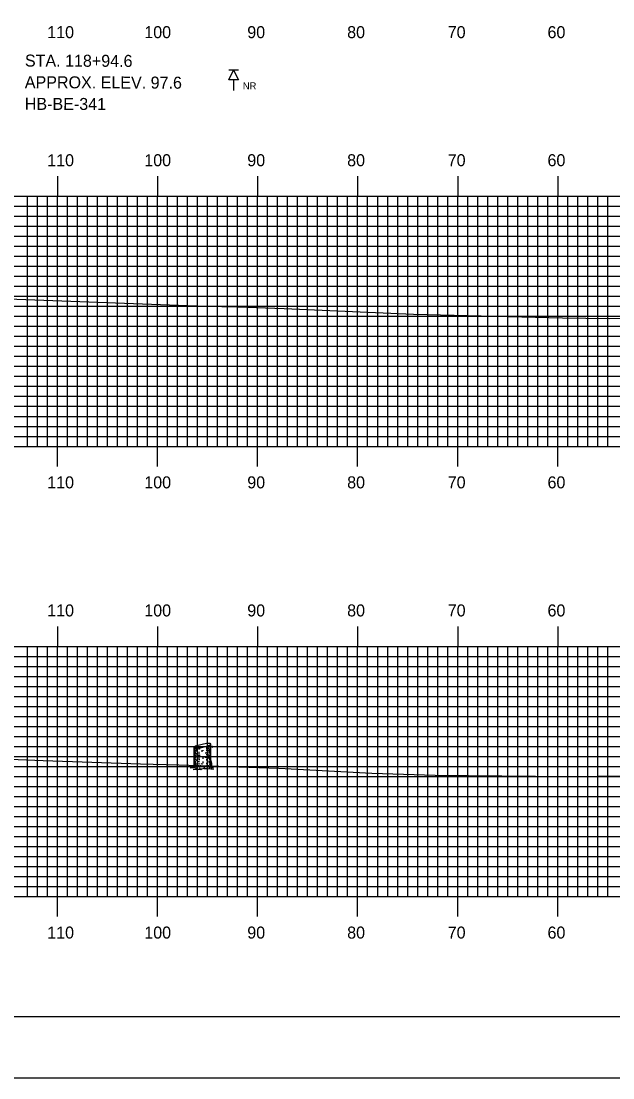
# Model space of a CAD drawing. Extents: x 1771629 to 1771972, y 442591 to 442811.
# Drawn here: x 1771681 to 1771740.1, y 442590.5 to 442696.2 of the extents above; entities that cross this region are included whole.
import ezdxf

# ---------------------------------------------------------------- set-up
doc = ezdxf.new("R2010")
doc.units = 0
for name, color, linetype in [('BORDER', 7, 'Continuous'), ('BORING - NO REFUSAL', 7, 'Continuous'), ('H_V ANNOTATION', 7, 'Continuous'), ('M_Trees_Conifer_Pay', 7, 'Continuous'), ('MAJOR', 7, 'Continuous'), ('MINOR', 7, 'Continuous'), ('PLOT BOUNDARY', 7, 'Continuous'), ('S_Roadway_Centerline', 7, 'Continuous')]:
    doc.layers.add(name, color=color, linetype=linetype)

msp = doc.modelspace()

# ---------------------------------------------------------------- linework, layer by layer
at = {"layer": 'BORDER'}
msp.add_lwpolyline([(1771644.98, 442596.67), (1771964.98, 442596.67), (1771964.98, 442806.67), (1771644.98, 442806.67)], close=True, dxfattribs=at)
at = {"layer": 'BORING - NO REFUSAL'}
for p, q in [((1771702.66, 442691.27), (1771701.7, 442691.27)), ((1771702.18, 442690.31), (1771702.18, 442689.25))]:
    msp.add_line(p, q, dxfattribs=at)
msp.add_lwpolyline([(1771702.18, 442691.27), (1771702.66, 442690.31), (1771701.7, 442690.31)], close=True, dxfattribs=at)
at = {"layer": 'M_Trees_Conifer_Pay'}
for p, q in [((1771698.25, 442621.86), (1771698.25, 442623.58)), ((1771699.49, 442623.59), (1771699.49, 442623.39)), ((1771699.72, 442623.78), (1771699.72, 442623.56)), ((1771699.84, 442623.84), (1771699.84, 442623.68)), ((1771699.84, 442623.61), (1771699.84, 442623.49)), ((1771699.91, 442622.27), (1771699.91, 442623.92)), ((1771698.29, 442623.54), (1771698.29, 442623.07)), ((1771698.29, 442623.01), (1771698.29, 442622.7)), ((1771698.29, 442622.65), (1771698.29, 442622.16)), ((1771698.35, 442623.53), (1771698.35, 442623.43)), ((1771698.35, 442623.36), (1771698.35, 442623.16)), ((1771698.35, 442623.1), (1771698.35, 442622.9)), ((1771698.35, 442622.85), (1771698.35, 442622.52)), ((1771698.48, 442623.52), (1771698.48, 442623.29)), ((1771698.48, 442623.25), (1771698.48, 442623.18)), ((1771698.48, 442622.77), (1771698.48, 442622.64)), ((1771698.7, 442623.54), (1771698.7, 442623.38)), ((1771698.7, 442623.14), (1771698.7, 442622.9)), ((1771698.7, 442622.66), (1771698.7, 442622.51)), ((1771699.1, 442623.31), (1771699.1, 442623.22)), ((1771699.1, 442622.7), (1771699.1, 442622.63)), ((1771699.1, 442622.6), (1771699.1, 442622.45)), ((1771699.49, 442623.33), (1771699.49, 442623.24)), ((1771699.49, 442622.89), (1771699.49, 442622.79)), ((1771699.72, 442623.47), (1771699.72, 442623.42)), ((1771699.72, 442623.09), (1771699.72, 442622.96)), ((1771699.72, 442622.85), (1771699.72, 442622.74)), ((1771699.72, 442622.6), (1771699.72, 442622.46)), ((1771699.78, 442623.29), (1771699.73, 442623.23)), ((1771699.84, 442623.3), (1771699.84, 442622.96)), ((1771699.84, 442622.93), (1771699.84, 442622.76)), ((1771699.84, 442622.72), (1771699.84, 442622.5)), ((1771698.29, 442622.11), (1771698.29, 442621.86)), ((1771698.35, 442622.46), (1771698.35, 442622.33)), ((1771698.35, 442622.23), (1771698.35, 442621.85)), ((1771698.48, 442622.36), (1771698.48, 442622.22)), ((1771698.48, 442621.96), (1771698.48, 442621.87)), ((1771698.48, 442621.47), (1771698.64, 442621.53)), ((1771698.7, 442622.46), (1771698.7, 442622.29)), ((1771698.7, 442622.01), (1771698.7, 442621.86)), ((1771698.91, 442621.4), (1771698.79, 442621.47)), ((1771699.1, 442622.16), (1771699.1, 442622.01)), ((1771699.49, 442622.42), (1771699.49, 442622.28)), ((1771699.49, 442622.04), (1771699.49, 442621.95)), ((1771699.72, 442622.23), (1771699.72, 442622.06)), ((1771699.84, 442622.47), (1771699.84, 442622.39)), ((1771699.84, 442622.35), (1771699.84, 442622.18))]:
    msp.add_line(p, q, dxfattribs=at)
for points in [[(1771699.73, 442623.41), (1771699.76, 442623.34), (1771699.81, 442623.4), (1771699.87, 442623.47), (1771699.96, 442623.66), (1771700.03, 442623.71), (1771700.06, 442623.71)], [(1771699.74, 442623.16), (1771699.78, 442623.29), (1771699.84, 442623.4), (1771699.87, 442623.47), (1771699.94, 442623.62)], [(1771699.96, 442623.65), (1771700.03, 442623.66), (1771700.1, 442623.56)], [(1771698.43, 442622.89), (1771698.42, 442622.98), (1771698.46, 442622.96), (1771698.46, 442622.86)], [(1771699.56, 442622.49), (1771699.58, 442622.41), (1771699.62, 442622.42), (1771699.61, 442622.59)], [(1771699.69, 442623.38), (1771699.66, 442623.29), (1771699.66, 442623.22), (1771699.69, 442623.16)], [(1771699.91, 442622.27), (1771699.96, 442622.01), (1771699.98, 442621.73), (1771700.04, 442621.61), (1771700.17, 442621.58), (1771699.94, 442621.54), (1771699.94, 442621.54), (1771699.95, 442621.49), (1771700.19, 442621.4), (1771699.92, 442621.41), (1771699.56, 442621.44), (1771699.24, 442621.42), (1771699.25, 442621.51), (1771699.1, 442621.42), (1771698.91, 442621.4), (1771698.94, 442621.33), (1771698.67, 442621.38), (1771698.45, 442621.35), (1771698.16, 442621.37), (1771698.45, 442621.42), (1771698.48, 442621.47), (1771698.31, 442621.52), (1771698.08, 442621.53), (1771697.84, 442621.53), (1771698.18, 442621.59), (1771698.22, 442621.67), (1771698.25, 442621.86)], [(1771698.29, 442621.81), (1771698.27, 442621.73), (1771698.25, 442621.64)], [(1771698.37, 442621.79), (1771698.38, 442621.68), (1771698.32, 442621.59), (1771698.31, 442621.52)], [(1771698.53, 442621.82), (1771698.53, 442621.69), (1771698.45, 442621.59)], [(1771698.76, 442621.58), (1771698.83, 442621.67), (1771698.86, 442621.81)], [(1771699.25, 442621.51), (1771699.32, 442621.65), (1771699.33, 442621.75)], [(1771699.5, 442621.88), (1771699.51, 442621.75), (1771699.58, 442621.71)], [(1771699.78, 442621.49), (1771699.76, 442621.62), (1771699.69, 442621.75)], [(1771699.74, 442621.98), (1771699.81, 442621.88), (1771699.82, 442621.7), (1771699.94, 442621.54)], [(1771699.84, 442622.13), (1771699.84, 442621.98), (1771699.89, 442621.91), (1771699.9, 442621.71)]]:
    msp.add_lwpolyline(points, dxfattribs=at)
for centre, radius, start, end in [((1771698.32, 442623.56), 0.0817, 132.3887, 146.7194), ((1771698.3, 442623.57), 0.0527, 146.7194, 156.5158), ((1771698.28, 442623.58), 0.0314, 156.5158, 169.2194), ((1771698.27, 442623.58), 0.0264, 169.2194, 180.0315), ((1771698.27, 442623.58), 0.0226, 180.0315, 191.7194), ((1771698.27, 442623.58), 0.0226, 191.7194, 203.4074), ((1771698.44, 442623.43), 0.251, 124.2194, 132.3887), ((1771698.74, 442622.97), 0.802, 108.0594, 124.2194), ((1771700.1, 442618.81), 5.18, 101.7194, 108.0594), ((1771698.05, 442628.68), 5.18, 275.3794, 281.7194), ((1771700.1, 442618.81), 5.18, 95.3794, 101.7194), ((1771698.05, 442628.68), 5.18, 281.7194, 288.0594), ((1771699.69, 442623.17), 0.802, 79.2194, 95.3794), ((1771699.41, 442624.52), 0.802, 288.0594, 304.2194), ((1771699.58, 442624.23), 0.571, 284.4317, 292.4132), ((1771699.79, 442623.71), 0.251, 71.0501, 79.2194), ((1771699.58, 442624.08), 0.571, 297.0237, 300), ((1771699.72, 442624.07), 0.251, 304.2194, 312.3887), ((1771699.78, 442623.88), 0.172, 300, 311.2506), ((1771699.78, 442623.73), 0.172, 300, 311.2506), ((1771699.85, 442623.87), 0.0817, 56.7194, 71.0501), ((1771699.87, 442623.9), 0.0527, 46.923, 56.7194), ((1771699.83, 442623.94), 0.0817, 312.3887, 326.7194), ((1771699.85, 442623.8), 0.0624, 311.2506, 330), ((1771699.85, 442623.65), 0.0624, 311.2506, 330), ((1771699.88, 442623.91), 0.0314, 34.2194, 46.923), ((1771699.86, 442623.93), 0.0527, 326.7194, 336.5158), ((1771699.87, 442623.79), 0.0441, 330, 343.9485), ((1771699.87, 442623.64), 0.0441, 330, 343.9485), ((1771699.89, 442623.92), 0.0226, 11.7194, 23.4074), ((1771699.88, 442623.91), 0.0264, 23.4074, 34.2194), ((1771699.88, 442623.92), 0.0264, 349.2194, 0.0315), ((1771699.89, 442623.92), 0.0226, 0.0315, 11.7194), ((1771699.88, 442623.92), 0.0314, 336.5158, 349.2194), ((1771699.88, 442623.79), 0.0334, 343.9485, 354.2151), ((1771699.88, 442623.64), 0.0334, 343.9485, 354.2151), ((1771698.28, 442623.4), 0.0334, 163.9485, 180), ((1771698.28, 442623.4), 0.0334, 180, 196.0515), ((1771698.28, 442622.96), 0.0334, 163.9485, 180), ((1771698.28, 442622.96), 0.0334, 180, 196.0515), ((1771698.28, 442622.75), 0.0334, 163.9485, 180), ((1771698.28, 442622.75), 0.0334, 180, 196.0515), ((1771698.28, 442622.51), 0.0334, 163.9485, 180), ((1771698.27, 442623.58), 0.0264, 203.4074, 214.2194), ((1771698.28, 442623.58), 0.0314, 214.2194, 226.923), ((1771698.29, 442623.6), 0.0527, 226.923, 236.7194), ((1771698.29, 442623.41), 0.0441, 196.0515, 210), ((1771698.3, 442623.41), 0.0624, 210, 228.7494), ((1771698.29, 442622.96), 0.0441, 196.0515, 210), ((1771698.3, 442622.97), 0.0624, 210, 228.7494), ((1771698.29, 442622.75), 0.0441, 196.0515, 210), ((1771698.3, 442622.76), 0.0624, 210, 228.7494), ((1771698.31, 442623.62), 0.0817, 236.7194, 251.0501), ((1771698.38, 442623.5), 0.172, 228.7494, 240), ((1771698.38, 442623.05), 0.172, 228.7494, 240), ((1771698.38, 442622.84), 0.172, 228.7494, 240), ((1771698.36, 442623.78), 0.251, 251.0501, 259.2194), ((1771698.58, 442623.84), 0.571, 240, 240.3367), ((1771698.58, 442623.63), 0.571, 240, 247.0587), ((1771698.58, 442623.4), 0.571, 240, 240.3367), ((1771698.58, 442623.19), 0.571, 240, 246.8597), ((1771698.46, 442624.33), 0.802, 259.2194, 275.3794), ((1771698.58, 442623.84), 0.571, 246.8597, 257.9846), ((1771698.58, 442623.19), 0.571, 259.2707, 261.8968), ((1771699.08, 442626.7), 4.12, 261.8968, 263.1474), ((1771699.08, 442626.91), 4.12, 264.081, 266.6676), ((1771699.08, 442627.59), 4.12, 264.6955, 266.7331), ((1771699.08, 442627.36), 4.12, 268.0751, 270), ((1771699.08, 442627.36), 4.12, 270, 270.3581), ((1771699.08, 442626.7), 4.12, 270, 270.3581), ((1771699.08, 442626.7), 4.12, 273.1493, 275.4569), ((1771699.08, 442627.15), 4.12, 273.7052, 275.9504), ((1771699.08, 442627.36), 4.12, 275.7849, 277.0558), ((1771699.08, 442627.59), 4.12, 276.238, 278.1032), ((1771699.08, 442626.91), 4.12, 277.6125, 278.1032), ((1771699.58, 442624.08), 0.571, 278.1032, 284.3667), ((1771699.58, 442623.4), 0.571, 278.1032, 286.9296), ((1771699.58, 442623.63), 0.571, 284.4493, 297.0429), ((1771699.58, 442623.4), 0.571, 297.1896, 300), ((1771699.58, 442623.19), 0.571, 297.1896, 300), ((1771699.78, 442623.05), 0.172, 300, 311.2506), ((1771699.78, 442622.84), 0.172, 300, 311.2506), ((1771699.85, 442622.97), 0.0624, 311.2506, 330), ((1771699.85, 442622.76), 0.0624, 311.2506, 330), ((1771699.87, 442622.96), 0.0441, 330, 343.9485), ((1771699.87, 442622.75), 0.0441, 330, 343.9485), ((1771699.88, 442623.19), 0.0334, 343.9485, 354.2151), ((1771699.88, 442622.96), 0.0334, 343.9485, 354.2151), ((1771699.88, 442622.75), 0.0334, 343.9485, 354.2151), ((1771698.28, 442622.51), 0.0334, 180, 196.0515), ((1771698.28, 442622.31), 0.0334, 163.9485, 180), ((1771698.28, 442622.12), 0.0334, 163.9485, 180), ((1771698.28, 442622.12), 0.0334, 180, 196.0515), ((1771698.28, 442621.9), 0.0334, 163.9485, 180), ((1771698.28, 442621.9), 0.0334, 180, 196.0515), ((1771698.29, 442622.51), 0.0441, 196.0515, 210), ((1771698.3, 442622.52), 0.0624, 210, 228.7494), ((1771698.29, 442622.12), 0.0441, 196.0515, 210), ((1771698.3, 442622.13), 0.0624, 210, 228.7494), ((1771698.29, 442621.9), 0.0441, 196.0515, 210), ((1771698.3, 442621.91), 0.0624, 210, 228.7494), ((1771698.38, 442622.6), 0.172, 228.7494, 240), ((1771698.38, 442622.21), 0.172, 228.7494, 240), ((1771698.38, 442621.99), 0.172, 228.7494, 240), ((1771698.58, 442622.95), 0.571, 240, 246.8597), ((1771698.57, 442622.76), 0.571, 241.2369, 248.0268), ((1771698.58, 442622.56), 0.571, 240, 246.8597), ((1771698.58, 442622.34), 0.571, 240, 244.5314), ((1771699.08, 442625.85), 4.12, 262.4438, 263.512), ((1771699.08, 442626.27), 4.12, 263.4991, 265.8397), ((1771699.08, 442626.47), 4.12, 264.716, 266.3193), ((1771699.08, 442626.07), 4.12, 267.8117, 270), ((1771699.08, 442626.07), 4.12, 270, 270.1328), ((1771699.08, 442626.07), 4.12, 275.7849, 276.7896), ((1771699.08, 442625.85), 4.12, 277.3684, 278.1032), ((1771699.58, 442622.34), 0.571, 278.1032, 281.637), ((1771699.58, 442622.95), 0.571, 285.3983, 297.1896), ((1771699.58, 442622.56), 0.571, 288.5067, 297.2721), ((1771699.58, 442622.75), 0.571, 289.2907, 300), ((1771699.78, 442622.41), 0.172, 300, 311.2506), ((1771699.78, 442621.99), 0.172, 300, 311.2506), ((1771699.85, 442622.32), 0.0624, 311.2506, 330), ((1771699.85, 442621.91), 0.0624, 311.2506, 330), ((1771699.87, 442622.31), 0.0441, 330, 343.9485), ((1771699.87, 442621.9), 0.0441, 330, 343.9485), ((1771699.88, 442622.31), 0.0334, 343.9485, 354.2151), ((1771699.88, 442621.9), 0.0334, 343.9485, 354.2151)]:
    msp.add_arc(centre, radius, start, end, dxfattribs=at)
at = {"layer": 'MAJOR'}
for p, q in [((1771684.58, 442680.67), (1771684.58, 442678.67)), ((1771694.58, 442680.67), (1771694.58, 442678.67)), ((1771704.58, 442680.67), (1771704.58, 442678.67)), ((1771714.58, 442680.67), (1771714.58, 442678.67)), ((1771724.58, 442680.67), (1771724.58, 442678.67)), ((1771734.58, 442680.67), (1771734.58, 442678.67)), ((1771654.58, 442678.67), (1771934.58, 442678.67)), ((1771654.58, 442678.67), (1771934.58, 442678.67)), ((1771684.58, 442653.67), (1771684.58, 442678.67)), ((1771694.58, 442653.67), (1771694.58, 442678.67)), ((1771704.58, 442653.67), (1771704.58, 442678.67)), ((1771714.58, 442653.67), (1771714.58, 442678.67)), ((1771724.58, 442653.67), (1771724.58, 442678.67)), ((1771734.58, 442653.67), (1771734.58, 442678.67)), ((1771654.58, 442673.67), (1771934.58, 442673.67)), ((1771654.58, 442668.67), (1771934.58, 442668.67)), ((1771654.58, 442663.67), (1771934.58, 442663.67)), ((1771654.58, 442658.67), (1771934.58, 442658.67)), ((1771654.58, 442653.67), (1771934.58, 442653.67)), ((1771654.58, 442653.67), (1771934.58, 442653.67)), ((1771684.58, 442651.66), (1771684.58, 442653.67)), ((1771694.58, 442651.66), (1771694.58, 442653.67)), ((1771704.58, 442651.66), (1771704.58, 442653.67)), ((1771714.58, 442651.66), (1771714.58, 442653.67)), ((1771724.58, 442651.66), (1771724.58, 442653.67)), ((1771734.58, 442651.66), (1771734.58, 442653.67)), ((1771684.58, 442635.67), (1771684.58, 442633.67)), ((1771694.58, 442635.67), (1771694.58, 442633.67)), ((1771704.58, 442635.67), (1771704.58, 442633.67)), ((1771714.58, 442635.67), (1771714.58, 442633.67)), ((1771724.58, 442635.67), (1771724.58, 442633.67)), ((1771734.58, 442635.67), (1771734.58, 442633.67)), ((1771654.58, 442633.67), (1771934.58, 442633.67)), ((1771654.58, 442633.67), (1771934.58, 442633.67)), ((1771684.58, 442608.67), (1771684.58, 442633.67)), ((1771694.58, 442608.67), (1771694.58, 442633.67)), ((1771704.58, 442608.67), (1771704.58, 442633.67)), ((1771714.58, 442608.67), (1771714.58, 442633.67)), ((1771724.58, 442608.67), (1771724.58, 442633.67)), ((1771734.58, 442608.67), (1771734.58, 442633.67)), ((1771654.58, 442628.67), (1771934.58, 442628.67)), ((1771654.58, 442623.67), (1771934.58, 442623.67)), ((1771654.58, 442618.67), (1771934.58, 442618.67)), ((1771654.58, 442613.67), (1771934.58, 442613.67)), ((1771654.58, 442608.67), (1771934.58, 442608.67)), ((1771654.58, 442608.67), (1771934.58, 442608.67)), ((1771684.58, 442606.66), (1771684.58, 442608.67)), ((1771694.58, 442606.66), (1771694.58, 442608.67)), ((1771704.58, 442606.66), (1771704.58, 442608.67)), ((1771714.58, 442606.66), (1771714.58, 442608.67)), ((1771724.58, 442606.66), (1771724.58, 442608.67)), ((1771734.58, 442606.66), (1771734.58, 442608.67))]:
    msp.add_line(p, q, dxfattribs=at)
at = {"layer": 'MINOR'}
for p, q in [((1771681.58, 442653.67), (1771681.58, 442678.67)), ((1771682.58, 442653.67), (1771682.58, 442678.67)), ((1771683.58, 442653.67), (1771683.58, 442678.67)), ((1771685.58, 442653.67), (1771685.58, 442678.67)), ((1771686.58, 442653.67), (1771686.58, 442678.67)), ((1771687.58, 442653.67), (1771687.58, 442678.67)), ((1771688.58, 442653.67), (1771688.58, 442678.67)), ((1771689.58, 442653.67), (1771689.58, 442678.67)), ((1771690.58, 442653.67), (1771690.58, 442678.67)), ((1771691.58, 442653.67), (1771691.58, 442678.67)), ((1771692.58, 442653.67), (1771692.58, 442678.67)), ((1771693.58, 442653.67), (1771693.58, 442678.67)), ((1771695.58, 442653.67), (1771695.58, 442678.67)), ((1771696.58, 442653.67), (1771696.58, 442678.67)), ((1771697.58, 442653.67), (1771697.58, 442678.67)), ((1771698.58, 442653.67), (1771698.58, 442678.67)), ((1771699.58, 442653.67), (1771699.58, 442678.67)), ((1771700.58, 442653.67), (1771700.58, 442678.67)), ((1771701.58, 442653.67), (1771701.58, 442678.67)), ((1771702.58, 442653.67), (1771702.58, 442678.67)), ((1771703.58, 442653.67), (1771703.58, 442678.67)), ((1771705.58, 442653.67), (1771705.58, 442678.67)), ((1771706.58, 442653.67), (1771706.58, 442678.67)), ((1771707.58, 442653.67), (1771707.58, 442678.67)), ((1771708.58, 442653.67), (1771708.58, 442678.67)), ((1771709.58, 442653.67), (1771709.58, 442678.67)), ((1771710.58, 442653.67), (1771710.58, 442678.67)), ((1771711.58, 442653.67), (1771711.58, 442678.67)), ((1771712.58, 442653.67), (1771712.58, 442678.67)), ((1771713.58, 442653.67), (1771713.58, 442678.67)), ((1771715.58, 442653.67), (1771715.58, 442678.67)), ((1771716.58, 442653.67), (1771716.58, 442678.67)), ((1771717.58, 442653.67), (1771717.58, 442678.67)), ((1771718.58, 442653.67), (1771718.58, 442678.67)), ((1771719.58, 442653.67), (1771719.58, 442678.67)), ((1771720.58, 442653.67), (1771720.58, 442678.67)), ((1771721.58, 442653.67), (1771721.58, 442678.67)), ((1771722.58, 442653.67), (1771722.58, 442678.67)), ((1771723.58, 442653.67), (1771723.58, 442678.67)), ((1771725.58, 442653.67), (1771725.58, 442678.67)), ((1771726.58, 442653.67), (1771726.58, 442678.67)), ((1771727.58, 442653.67), (1771727.58, 442678.67)), ((1771728.58, 442653.67), (1771728.58, 442678.67)), ((1771729.58, 442653.67), (1771729.58, 442678.67)), ((1771730.58, 442653.67), (1771730.58, 442678.67)), ((1771731.58, 442653.67), (1771731.58, 442678.67)), ((1771732.58, 442653.67), (1771732.58, 442678.67)), ((1771733.58, 442653.67), (1771733.58, 442678.67)), ((1771735.58, 442653.67), (1771735.58, 442678.67)), ((1771736.58, 442653.67), (1771736.58, 442678.67)), ((1771737.58, 442653.67), (1771737.58, 442678.67)), ((1771738.58, 442653.67), (1771738.58, 442678.67)), ((1771739.58, 442653.67), (1771739.58, 442678.67)), ((1771654.58, 442677.67), (1771934.58, 442677.67)), ((1771654.58, 442676.67), (1771934.58, 442676.67)), ((1771654.58, 442675.67), (1771934.58, 442675.67)), ((1771654.58, 442674.67), (1771934.58, 442674.67)), ((1771654.58, 442672.67), (1771934.58, 442672.67)), ((1771654.58, 442671.67), (1771934.58, 442671.67)), ((1771654.58, 442670.67), (1771934.58, 442670.67)), ((1771654.58, 442669.67), (1771934.58, 442669.67)), ((1771654.58, 442667.67), (1771934.58, 442667.67)), ((1771654.58, 442666.67), (1771934.58, 442666.67)), ((1771654.58, 442665.67), (1771934.58, 442665.67)), ((1771654.58, 442664.67), (1771934.58, 442664.67)), ((1771654.58, 442662.67), (1771934.58, 442662.67)), ((1771654.58, 442661.67), (1771934.58, 442661.67)), ((1771654.58, 442660.67), (1771934.58, 442660.67)), ((1771654.58, 442659.67), (1771934.58, 442659.67)), ((1771654.58, 442657.67), (1771934.58, 442657.67)), ((1771654.58, 442656.67), (1771934.58, 442656.67)), ((1771654.58, 442655.67), (1771934.58, 442655.67)), ((1771654.58, 442654.67), (1771934.58, 442654.67)), ((1771681.58, 442608.67), (1771681.58, 442633.67)), ((1771682.58, 442608.67), (1771682.58, 442633.67)), ((1771683.58, 442608.67), (1771683.58, 442633.67)), ((1771685.58, 442608.67), (1771685.58, 442633.67)), ((1771686.58, 442608.67), (1771686.58, 442633.67)), ((1771687.58, 442608.67), (1771687.58, 442633.67)), ((1771688.58, 442608.67), (1771688.58, 442633.67)), ((1771689.58, 442608.67), (1771689.58, 442633.67)), ((1771690.58, 442608.67), (1771690.58, 442633.67)), ((1771691.58, 442608.67), (1771691.58, 442633.67)), ((1771692.58, 442608.67), (1771692.58, 442633.67)), ((1771693.58, 442608.67), (1771693.58, 442633.67)), ((1771695.58, 442608.67), (1771695.58, 442633.67)), ((1771696.58, 442608.67), (1771696.58, 442633.67)), ((1771697.58, 442608.67), (1771697.58, 442633.67)), ((1771698.58, 442608.67), (1771698.58, 442633.67)), ((1771699.58, 442608.67), (1771699.58, 442633.67)), ((1771700.58, 442608.67), (1771700.58, 442633.67)), ((1771701.58, 442608.67), (1771701.58, 442633.67)), ((1771702.58, 442608.67), (1771702.58, 442633.67)), ((1771703.58, 442608.67), (1771703.58, 442633.67)), ((1771705.58, 442608.67), (1771705.58, 442633.67)), ((1771706.58, 442608.67), (1771706.58, 442633.67)), ((1771707.58, 442608.67), (1771707.58, 442633.67)), ((1771708.58, 442608.67), (1771708.58, 442633.67)), ((1771709.58, 442608.67), (1771709.58, 442633.67)), ((1771710.58, 442608.67), (1771710.58, 442633.67)), ((1771711.58, 442608.67), (1771711.58, 442633.67)), ((1771712.58, 442608.67), (1771712.58, 442633.67)), ((1771713.58, 442608.67), (1771713.58, 442633.67)), ((1771715.58, 442608.67), (1771715.58, 442633.67)), ((1771716.58, 442608.67), (1771716.58, 442633.67)), ((1771717.58, 442608.67), (1771717.58, 442633.67)), ((1771718.58, 442608.67), (1771718.58, 442633.67)), ((1771719.58, 442608.67), (1771719.58, 442633.67)), ((1771720.58, 442608.67), (1771720.58, 442633.67)), ((1771721.58, 442608.67), (1771721.58, 442633.67)), ((1771722.58, 442608.67), (1771722.58, 442633.67)), ((1771723.58, 442608.67), (1771723.58, 442633.67)), ((1771725.58, 442608.67), (1771725.58, 442633.67)), ((1771726.58, 442608.67), (1771726.58, 442633.67)), ((1771727.58, 442608.67), (1771727.58, 442633.67)), ((1771728.58, 442608.67), (1771728.58, 442633.67)), ((1771729.58, 442608.67), (1771729.58, 442633.67)), ((1771730.58, 442608.67), (1771730.58, 442633.67)), ((1771731.58, 442608.67), (1771731.58, 442633.67)), ((1771732.58, 442608.67), (1771732.58, 442633.67)), ((1771733.58, 442608.67), (1771733.58, 442633.67)), ((1771735.58, 442608.67), (1771735.58, 442633.67)), ((1771736.58, 442608.67), (1771736.58, 442633.67)), ((1771737.58, 442608.67), (1771737.58, 442633.67)), ((1771738.58, 442608.67), (1771738.58, 442633.67)), ((1771739.58, 442608.67), (1771739.58, 442633.67)), ((1771654.58, 442632.67), (1771934.58, 442632.67)), ((1771654.58, 442631.67), (1771934.58, 442631.67)), ((1771654.58, 442630.67), (1771934.58, 442630.67)), ((1771654.58, 442629.67), (1771934.58, 442629.67)), ((1771654.58, 442627.67), (1771934.58, 442627.67)), ((1771654.58, 442626.67), (1771934.58, 442626.67)), ((1771654.58, 442625.67), (1771934.58, 442625.67)), ((1771654.58, 442624.67), (1771934.58, 442624.67)), ((1771654.58, 442622.67), (1771934.58, 442622.67)), ((1771654.58, 442621.67), (1771934.58, 442621.67)), ((1771654.58, 442620.67), (1771934.58, 442620.67)), ((1771654.58, 442619.67), (1771934.58, 442619.67)), ((1771654.58, 442617.67), (1771934.58, 442617.67)), ((1771654.58, 442616.67), (1771934.58, 442616.67)), ((1771654.58, 442615.67), (1771934.58, 442615.67)), ((1771654.58, 442614.67), (1771934.58, 442614.67)), ((1771654.58, 442612.67), (1771934.58, 442612.67)), ((1771654.58, 442611.67), (1771934.58, 442611.67)), ((1771654.58, 442610.67), (1771934.58, 442610.67)), ((1771654.58, 442609.67), (1771934.58, 442609.67))]:
    msp.add_line(p, q, dxfattribs=at)
at = {"layer": 'PLOT BOUNDARY'}
msp.add_lwpolyline([(1771628.79, 442590.55), (1771968.79, 442590.55), (1771968.79, 442810.55), (1771628.79, 442810.55)], close=True, dxfattribs=at)
at = {"layer": 'S_Roadway_Centerline'}
for points in [[(1771654.58, 442669.48), (1771656.04, 442669.36), (1771659.63, 442669.23), (1771668, 442668.8), (1771679.66, 442668.42), (1771680.08, 442668.4), (1771680.54, 442668.38), (1771699.38, 442667.69), (1771702.61, 442667.61), (1771707.23, 442667.46), (1771720.16, 442666.88), (1771735.05, 442666.53), (1771739.7, 442666.46), (1771749.35, 442666.64)], [(1771654.58, 442623.4), (1771655.33, 442623.39), (1771659.61, 442623.3), (1771665.66, 442622.98), (1771683.17, 442622.26), (1771692.87, 442621.95), (1771696.7, 442621.83), (1771706.7, 442621.49), (1771715.99, 442621.01), (1771722.32, 442620.81), (1771735.69, 442620.67), (1771741.62, 442620.72)]]:
    msp.add_lwpolyline(points, dxfattribs=at)

# ---------------------------------------------------------------- texts
at = {"layer": 'BORING - NO REFUSAL'}
for s, p in [('STA. 118+94.6', (1771681.33, 442691.63)), ('APPROX. ELEV. 97.6', (1771681.32, 442689.47)), ('HB-BE-341', (1771681.32, 442687.31))]:
    msp.add_text(s, height=1.2, rotation=359.8142, dxfattribs=at).set_placement(p)
msp.add_text('NR', height=0.7, dxfattribs=at).set_placement((1771703.11, 442689.35))
at = {"layer": 'H_V ANNOTATION'}
for s, p in [('110', (1771683.56, 442694.47)), ('100', (1771693.26, 442694.47)), ('90', (1771703.55, 442694.47)), ('80', (1771713.53, 442694.47)), ('70', (1771723.58, 442694.47)), ('60', (1771733.55, 442694.47)), ('110', (1771683.56, 442681.67)), ('100', (1771693.26, 442681.67)), ('90', (1771703.55, 442681.67)), ('80', (1771713.53, 442681.67)), ('70', (1771723.58, 442681.67)), ('60', (1771733.55, 442681.67)), ('110', (1771683.56, 442649.47)), ('100', (1771693.26, 442649.47)), ('90', (1771703.55, 442649.47)), ('80', (1771713.53, 442649.47)), ('70', (1771723.58, 442649.47)), ('60', (1771733.55, 442649.47)), ('110', (1771683.56, 442636.67)), ('100', (1771693.26, 442636.67)), ('90', (1771703.55, 442636.67)), ('80', (1771713.53, 442636.67)), ('70', (1771723.58, 442636.67)), ('60', (1771733.55, 442636.67)), ('110', (1771683.56, 442604.47)), ('100', (1771693.26, 442604.47)), ('90', (1771703.55, 442604.47)), ('80', (1771713.53, 442604.47)), ('70', (1771723.58, 442604.47)), ('60', (1771733.55, 442604.47))]:
    msp.add_text(s, height=1.2, dxfattribs=at).set_placement(p)

doc.saveas('drawing.dxf')
